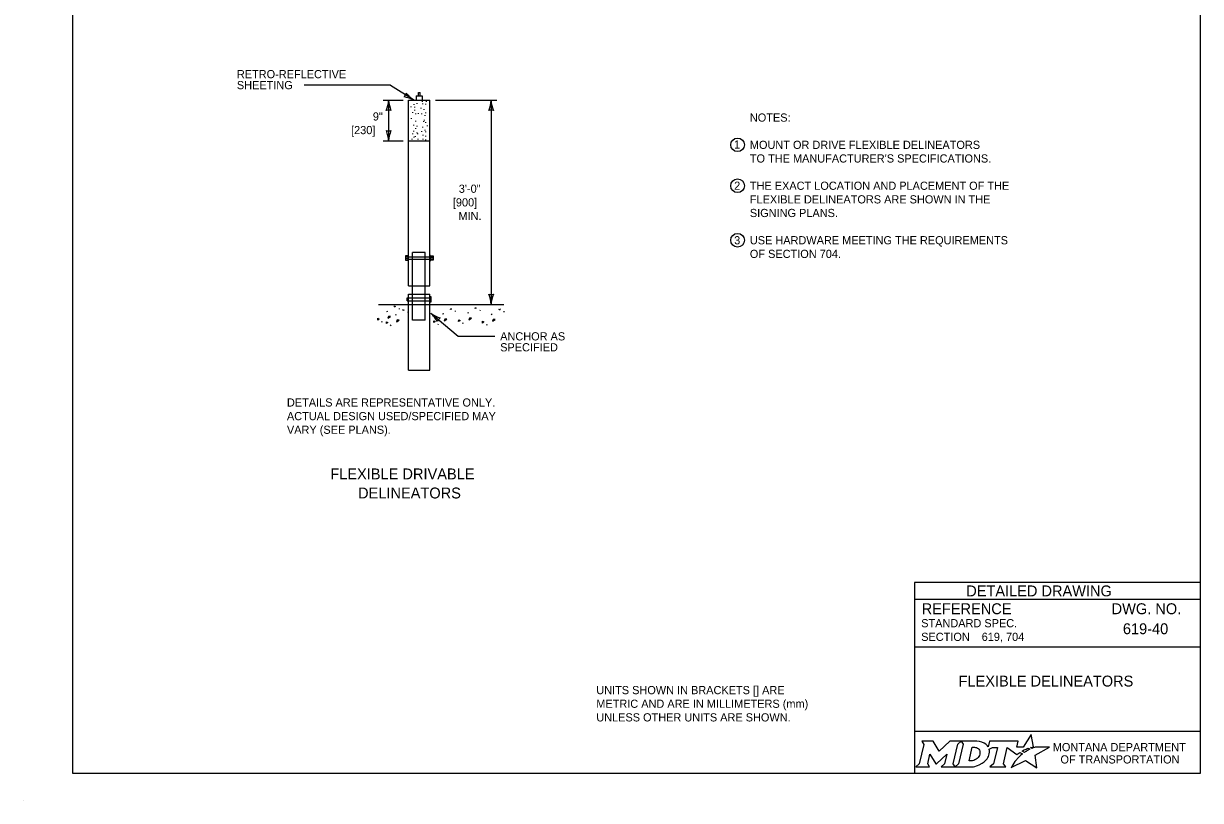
# Model space of a CAD drawing. Extents: x 49991.4 to 50021, y 49987.6 to 50011.4.
# Drawn here: x 49999.98 to 50008.61, y 49999.86 to 50005.56 of the extents above; entities that cross this region are included whole.
import ezdxf

# ---------------------------------------------------------------- set-up
doc = ezdxf.new("R2010")
doc.units = 0
for name, color, linetype in [('Level 1', 7, 'Continuous'), ('Level 2', 7, 'Continuous'), ('Level 3', 7, 'Continuous'), ('Level 4', 7, 'Continuous')]:
    doc.layers.add(name, color=color, linetype=linetype)

msp = doc.modelspace()

# ---------------------------------------------------------------- linework, layer by layer
at = {"layer": 'Level 1'}
for p, q in [((50002.8744, 50005.0555), (50002.8866, 50005.0555)), ((50002.8744, 50005.032), (50002.8744, 50005.0555)), ((50002.8866, 50005.032), (50002.8866, 50005.0555)), ((50002.8029, 50005.001), (50002.9591, 50005.001)), ((50002.8029, 50003.6384), (50002.8029, 50005.001)), ((50002.8226, 50004.9479), (50002.8226, 50004.9528)), ((50002.8293, 50004.9948), (50002.8293, 50004.9997)), ((50002.8429, 50004.9663), (50002.8429, 50004.9712)), ((50002.848, 50004.946), (50002.848, 50004.9509)), ((50002.8583, 50005.032), (50002.8583, 50005.0012)), ((50002.8583, 50005.032), (50002.9035, 50005.032)), ((50002.8656, 50004.9732), (50002.8656, 50004.978)), ((50002.9035, 50005.032), (50002.9035, 50005.0012)), ((50002.9039, 50004.988), (50002.9039, 50004.9929)), ((50002.9074, 50004.971), (50002.9074, 50004.9759)), ((50002.9284, 50004.9697), (50002.9284, 50004.9745)), ((50002.9331, 50004.9873), (50002.9331, 50004.9922)), ((50002.9591, 50003.6384), (50002.9591, 50005.001)), ((50002.8246, 50004.8632), (50002.8246, 50004.868)), ((50002.8348, 50004.9087), (50002.8348, 50004.9135)), ((50002.848, 50004.9257), (50002.848, 50004.9305)), ((50002.8561, 50004.8985), (50002.8561, 50004.9034)), ((50002.8744, 50004.8992), (50002.8744, 50004.904)), ((50002.8948, 50004.9405), (50002.8948, 50004.9454)), ((50002.9005, 50004.8984), (50002.9005, 50004.9033)), ((50002.9169, 50004.9297), (50002.9169, 50004.9345)), ((50002.9236, 50004.8863), (50002.9236, 50004.8912)), ((50002.9304, 50004.9045), (50002.9304, 50004.9094)), ((50002.8415, 50004.8137), (50002.8415, 50004.8185)), ((50002.8554, 50004.7907), (50002.8554, 50004.7955)), ((50002.8561, 50004.8442), (50002.8561, 50004.849)), ((50002.8649, 50004.8069), (50002.8649, 50004.8118)), ((50002.908, 50004.8008), (50002.908, 50004.8057)), ((50002.9141, 50004.8414), (50002.9141, 50004.8463)), ((50002.9203, 50004.8523), (50002.9203, 50004.8572)), ((50002.9236, 50004.7777), (50002.9236, 50004.7825)), ((50002.9284, 50004.8347), (50002.9284, 50004.8395)), ((50002.9413, 50004.8089), (50002.9413, 50004.8138)), ((50002.8029, 50004.701), (50002.9591, 50004.701)), ((50002.8293, 50004.7119), (50002.8293, 50004.7168)), ((50002.8328, 50004.7499), (50002.8328, 50004.7548)), ((50002.8423, 50004.7717), (50002.8423, 50004.7765)), ((50002.8425, 50004.7255), (50002.8425, 50004.7304)), ((50002.8534, 50004.7317), (50002.8534, 50004.7365)), ((50002.8656, 50004.7594), (50002.8656, 50004.7643)), ((50002.8696, 50004.7507), (50002.8696, 50004.7555)), ((50002.8724, 50004.7119), (50002.8724, 50004.7168)), ((50002.9005, 50004.7669), (50002.9005, 50004.7718)), ((50002.9086, 50004.7404), (50002.9086, 50004.7453)), ((50002.9108, 50004.7125), (50002.9108, 50004.7174)), ((50002.9304, 50004.7648), (50002.9304, 50004.7697)), ((50002.9304, 50004.7329), (50002.9304, 50004.7378)), ((50002.9304, 50004.7078), (50002.9304, 50004.7127)), ((50002.7992, 50003.8475), (50002.78, 50003.8475)), ((50002.7992, 50003.8363), (50002.78, 50003.8363)), ((50002.8029, 50003.851), (50002.9591, 50003.851)), ((50002.8029, 50003.8328), (50002.9591, 50003.8328)), ((50002.9629, 50003.8475), (50002.9821, 50003.8475)), ((50002.9629, 50003.8363), (50002.9821, 50003.8363)), ((50002.8029, 50003.6384), (50002.9591, 50003.6384)), ((50002.8029, 50003.576), (50002.9591, 50003.576)), ((50002.8029, 50003.0205), (50002.8029, 50003.576)), ((50002.8322, 50003.578), (50002.8322, 50003.6404)), ((50002.9246, 50003.576), (50002.9246, 50003.6384)), ((50002.9591, 50003.0205), (50002.9591, 50003.576)), ((50002.5807, 50003.5004), (50003.5005, 50003.5004)), ((50002.6972, 50003.483), (50002.7005, 50003.4907)), ((50002.7045, 50003.4848), (50002.6972, 50003.483)), ((50002.7005, 50003.4907), (50002.7045, 50003.4848)), ((50002.7919, 50003.5512), (50002.9591, 50003.5512)), ((50002.7919, 50003.5281), (50002.7919, 50003.5512)), ((50002.7919, 50003.5281), (50002.9591, 50003.5281)), ((50002.9591, 50003.5203), (50002.9682, 50003.5203)), ((50002.5759, 50003.3867), (50002.5767, 50003.4003)), ((50002.5767, 50003.4003), (50002.5862, 50003.3948)), ((50002.6479, 50003.4506), (50002.6402, 50003.4481)), ((50002.6553, 50003.4128), (50002.6502, 50003.3999)), ((50002.6502, 50003.3999), (50002.67, 50003.4124)), ((50002.67, 50003.4124), (50002.6553, 50003.4128)), ((50002.7123, 50003.4255), (50002.7046, 50003.423)), ((50002.735, 50003.4672), (50002.7357, 50003.473)), ((50002.7616, 50003.4579), (50002.7649, 50003.4656)), ((50002.7689, 50003.4597), (50002.7616, 50003.4579)), ((50002.7649, 50003.4656), (50002.7689, 50003.4597)), ((50002.7994, 50003.4421), (50002.8001, 50003.4479)), ((50003.0603, 50003.4322), (50003.0526, 50003.4297)), ((50003.1096, 50003.4646), (50003.1129, 50003.4723)), ((50003.1169, 50003.4664), (50003.1096, 50003.4646)), ((50003.1129, 50003.4723), (50003.1169, 50003.4664)), ((50003.1474, 50003.4488), (50003.1481, 50003.4546)), ((50003.2418, 50003.4398), (50003.2341, 50003.4373)), ((50003.2492, 50003.402), (50003.2441, 50003.3891)), ((50003.2441, 50003.3891), (50003.2639, 50003.4016)), ((50003.2639, 50003.4016), (50003.2492, 50003.402)), ((50003.2911, 50003.4722), (50003.2944, 50003.4799)), ((50003.2984, 50003.474), (50003.2911, 50003.4722)), ((50003.2944, 50003.4799), (50003.2984, 50003.474)), ((50003.3289, 50003.4564), (50003.3296, 50003.4622)), ((50003.4171, 50003.4291), (50003.4094, 50003.4266)), ((50003.4664, 50003.4615), (50003.4697, 50003.4692)), ((50003.4737, 50003.4633), (50003.4664, 50003.4615)), ((50003.4697, 50003.4692), (50003.4737, 50003.4633)), ((50003.5042, 50003.4457), (50003.5049, 50003.4515)), ((50002.5862, 50003.3948), (50002.5759, 50003.3867)), ((50002.6068, 50003.3764), (50002.6042, 50003.3695)), ((50002.6403, 50003.3616), (50002.6411, 50003.3752)), ((50002.6506, 50003.3697), (50002.6403, 50003.3616)), ((50002.6411, 50003.3752), (50002.6506, 50003.3697)), ((50002.6712, 50003.3513), (50002.6686, 50003.3444)), ((50002.7197, 50003.3877), (50002.7146, 50003.3748)), ((50002.7146, 50003.3748), (50002.7344, 50003.3873)), ((50002.7344, 50003.3873), (50002.7197, 50003.3877)), ((50002.9883, 50003.3683), (50002.9891, 50003.3819)), ((50002.9986, 50003.3764), (50002.9883, 50003.3683)), ((50002.9891, 50003.3819), (50002.9986, 50003.3764)), ((50003.0192, 50003.358), (50003.0166, 50003.3511)), ((50003.0677, 50003.3944), (50003.0626, 50003.3815)), ((50003.0626, 50003.3815), (50003.0824, 50003.394)), ((50003.0824, 50003.394), (50003.0677, 50003.3944)), ((50003.1698, 50003.3759), (50003.1706, 50003.3895)), ((50003.1801, 50003.384), (50003.1698, 50003.3759)), ((50003.1706, 50003.3895), (50003.1801, 50003.384)), ((50003.2007, 50003.3656), (50003.1981, 50003.3587)), ((50003.3451, 50003.3652), (50003.3459, 50003.3788)), ((50003.3554, 50003.3733), (50003.3451, 50003.3652)), ((50003.3459, 50003.3788), (50003.3554, 50003.3733)), ((50003.376, 50003.3549), (50003.3734, 50003.348)), ((50003.4245, 50003.3913), (50003.4194, 50003.3784)), ((50003.4194, 50003.3784), (50003.4392, 50003.3909)), ((50003.4392, 50003.3909), (50003.4245, 50003.3913)), ((50002.8029, 50003.0205), (50002.9591, 50003.0205)), ((49999.9766, 49999.8624), (49999.9766, 49999.8624))]:
    msp.add_line(p, q, dxfattribs=at)
msp.add_lwpolyline([(50008.6146, 50011.2628), (50000.3356, 50011.2628), (50000.3356, 50000.0624), (50008.6146, 50000.0624)], close=True, dxfattribs=at)
for points in [[(50002.7992, 50003.8572), (50002.78, 50003.8572), (50002.78, 50003.8253), (50002.7992, 50003.8253)], [(50002.803, 50003.8205), (50002.7992, 50003.8205), (50002.7992, 50003.8613), (50002.803, 50003.8611)], [(50002.9591, 50003.8205), (50002.9629, 50003.8205), (50002.9629, 50003.8613), (50002.9591, 50003.8611)], [(50002.9629, 50003.8572), (50002.9821, 50003.8572), (50002.9821, 50003.8253), (50002.9629, 50003.8253)], [(50002.9682, 50003.5203), (50002.9682, 50003.5581), (50002.9591, 50003.5581)]]:
    msp.add_lwpolyline(points, dxfattribs=at)
at = {"layer": 'Level 2'}
for p, q in [((50008.6146, 50001.4624), (50006.5146, 50001.4624)), ((50006.5146, 50001.4624), (50006.5146, 50000.0624)), ((50008.6146, 50001.3374), (50006.5146, 50001.3374)), ((50008.2507, 50001.1223), (50008.2507, 50001.1223)), ((50008.6146, 50000.9874), (50006.5146, 50000.9874)), ((50007.0089, 50001.0629), (50007.0089, 50001.0629)), ((50007.5646, 50000.7383), (50007.5646, 50000.7383)), ((50008.6146, 50000.3693), (50006.5146, 50000.3693))]:
    msp.add_line(p, q, dxfattribs=at)
for points in [[(50006.5701, 50000.2974), (50006.5842, 50000.274), (50006.5507, 50000.1307), (50006.525, 50000.1082), (50006.6266, 50000.1082), (50006.6131, 50000.131), (50006.6293, 50000.2011), (50006.673, 50000.1321), (50006.6783, 50000.1321), (50006.7534, 50000.2016), (50006.737, 50000.1305), (50006.7123, 50000.1085), (50006.8139, 50000.1085), (50006.8001, 50000.1318), (50006.8333, 50000.2742)], [(50006.8333, 50000.2742), (50006.8586, 50000.2974), (50006.7762, 50000.2974), (50006.6966, 50000.2244), (50006.6521, 50000.2971), (50006.5701, 50000.2974)], [(50006.9722, 50000.2974), (50006.8586, 50000.2974), (50006.8733, 50000.2745), (50006.8394, 50000.1307), (50006.8139, 50000.1085), (50006.9245, 50000.1085)], [(50007.3771, 50000.2447), (50007.3668, 50000.2503), (50007.3784, 50000.2531), (50007.39, 50000.2551), (50007.3726, 50000.3452), (50007.3131, 50000.2539), (50007.2658, 50000.2532), (50007.2761, 50000.2973), (50007.0669, 50000.2974), (50007.0568, 50000.2549), (50007.051, 50000.2632)], [(50006.9962, 50000.2107), (50006.995, 50000.2026), (50006.9918, 50000.1933), (50006.9876, 50000.1851), (50006.982, 50000.1776), (50006.9755, 50000.1707), (50006.9676, 50000.1644), (50006.9593, 50000.1597), (50006.9502, 50000.1558), (50006.9411, 50000.1535), (50006.9319, 50000.1526), (50006.916, 50000.1526), (50006.9396, 50000.2526), (50006.9556, 50000.2526), (50006.9632, 50000.252), (50006.9708, 50000.2501), (50006.9774, 50000.2471), (50006.9835, 50000.2429), (50006.9883, 50000.2379), (50006.992, 50000.2319), (50006.9947, 50000.2257), (50006.9963, 50000.2183), (50006.9963, 50000.2153), (50006.9962, 50000.2107)], [(50007.0636, 50000.2383), (50007.0882, 50000.2514), (50007.1251, 50000.2514), (50007.0965, 50000.1309), (50007.069, 50000.1082), (50007.1852, 50000.1082), (50007.1682, 50000.1311), (50007.1964, 50000.2513), (50007.2677, 50000.1996), (50007.2888, 50000.2147), (50007.3085, 50000.2038)], [(50007.2527, 50000.1479), (50007.2374, 50000.1235), (50007.2327, 50000.116), (50007.2269, 50000.1074), (50007.2246, 50000.1031), (50007.3299, 50000.1562), (50007.4138, 50000.1011), (50007.4007, 50000.1938), (50007.5076, 50000.2522), (50007.4583, 50000.253), (50007.4282, 50000.2534), (50007.4074, 50000.2537), (50007.4006, 50000.2522), (50007.3957, 50000.251), (50007.3873, 50000.2487), (50007.3771, 50000.2447)], [(50007.3267, 50000.2171), (50007.3243, 50000.2154), (50007.306, 50000.225), (50007.3163, 50000.2307), (50007.3204, 50000.2329), (50007.329, 50000.2369), (50007.3347, 50000.2395), (50007.3426, 50000.2425), (50007.3499, 50000.2452), (50007.3617, 50000.2378), (50007.3577, 50000.2357), (50007.3531, 50000.2332), (50007.3489, 50000.231), (50007.3439, 50000.2281), (50007.342, 50000.227), (50007.3393, 50000.2254), (50007.3368, 50000.224), (50007.3345, 50000.2224), (50007.3319, 50000.2206), (50007.3292, 50000.2188), (50007.3267, 50000.2171)], [(50006.9702, 50000.1158), (50006.9786, 50000.1184), (50006.9916, 50000.1238), (50007.012, 50000.1348)], [(50007.2666, 50000.164), (50007.2666, 50000.164)]]:
    msp.add_lwpolyline(points, dxfattribs=at)
for centre in [(50005.2174, 50004.6727), (50005.2174, 50004.3727), (50005.2174, 50003.9727)]:
    msp.add_circle(centre, 0.05, dxfattribs=at)
for centre, radius, start, end in [((50006.9953, 50000.219), 0.0709, 339.53292, 15.85821), ((50006.9513, 50000.2363), 0.1183, 300.91025, 339.13831)]:
    msp.add_arc(centre, radius, start, end, dxfattribs=at)
for centre, major_axis, ratio, start_param, end_param in [((50006.9701, 50000.25), (0.0834, -0.0037), 0.568097, 0.61298, 1.570796), ((50007.0257, 50000.2573), (0.0361, -0.0295), 0.469099, 1.225588, 1.570796), ((50007.2974, 50000.1941), (-0.0112, -0.0097), 0.021651, 3.157348, 6.283185), ((50006.9248, 50000.2568), (0, 0.1484), 0.987302, 3.139398, 3.456847), ((50007.2597, 50000.1559), (-0.00694, -0.00806), 0.008222, 0, 3.137361), ((50007.2764, 50000.1742), (-0.0098, -0.0102), 0.016458, 3.141593, 6.279097)]:
    msp.add_ellipse(centre, major_axis=major_axis, ratio=ratio, start_param=start_param, end_param=end_param, dxfattribs=at)
at = {"layer": 'Level 3'}
for p, q in [((50002.6689, 50005.111), (50002.0373, 50005.111)), ((50002.6689, 50005.111), (50002.8379, 50005.0042)), ((50002.6162, 50005.001), (50002.7629, 50005.001)), ((50002.6562, 50005.001), (50002.6562, 50004.701)), ((50002.9991, 50005.001), (50003.0842, 50005.001)), ((50003.0842, 50005.001), (50003.451, 50005.001)), ((50003.4081, 50005.001), (50003.4081, 50003.5004)), ((50002.6162, 50004.701), (50002.7629, 50004.701)), ((50002.9657, 50003.4375), (50003.1677, 50003.2677)), ((50003.1677, 50003.2677), (50003.4349, 50003.2677))]:
    msp.add_line(p, q, dxfattribs=at)
for centre, radius, start, end in [((50002.7323, 50005.0643), 0.0548, 312.30837, 348.03073), ((50002.962, 50005.1887), 0.2223, 217.62556, 237.80907), ((50002.434, 50005.0102), 0.2223, 337.45601, 357.63952), ((50002.8889, 50005.0125), 0.233, 182.82731, 202.07716), ((50002.7378, 50004.793), 0.233, 62.99686, 82.24671), ((50003.186, 50005.0102), 0.2223, 337.45601, 357.63952), ((50003.6408, 50005.0125), 0.233, 182.82731, 202.07716), ((50002.6562, 50004.8728), 0.0548, 72.13882, 107.86118), ((50003.4081, 50004.8728), 0.0548, 72.13882, 107.86118), ((50002.6562, 50004.8292), 0.0548, 252.13882, 287.86118), ((50002.4235, 50004.6895), 0.233, 2.82731, 22.07716), ((50002.8783, 50004.6918), 0.2223, 157.45601, 177.63952), ((50003.4081, 50003.6286), 0.0548, 252.13882, 287.86118), ((50003.1754, 50003.4889), 0.233, 2.82731, 22.07716), ((50003.6302, 50003.4912), 0.2223, 157.45601, 177.63952), ((50002.8177, 50003.2716), 0.2223, 28.11129, 48.2948), ((50003.1043, 50003.6248), 0.233, 233.48259, 252.73244), ((50003.0648, 50003.3563), 0.0548, 122.7941, 158.51646)]:
    msp.add_arc(centre, radius, start, end, dxfattribs=at)
at = {"layer": 'Level 4'}
for p, q in [((50002.8322, 50003.3859), (50002.8322, 50003.8822)), ((50002.9246, 50003.8822), (50002.8322, 50003.8822)), ((50002.9246, 50003.3859), (50002.9246, 50003.8822)), ((50002.9246, 50003.3859), (50002.8322, 50003.3859))]:
    msp.add_line(p, q, dxfattribs=at)

# ---------------------------------------------------------------- texts
at = {"layer": 'Level 2'}
for s, height, p in [('RETRO-REFLECTIVE ', 0.06, (50001.5424, 50005.1614)), ('SHEETING', 0.06, (50001.5424, 50005.081)), ('9"', 0.06, (50002.5402, 50004.851)), ('NOTES:', 0.06, (50005.3074, 50004.8427)), ('[230]', 0.06, (50002.3805, 50004.751)), ('1', 0.06, (50005.1916, 50004.6453)), ('MOUNT OR DRIVE FLEXIBLE DELINEATORS', 0.06, (50005.3074, 50004.6427)), ("TO THE MANUFACTURER'S SPECIFICATIONS.", 0.06, (50005.3074, 50004.5427)), ('3\'-0"', 0.06, (50003.1712, 50004.3207)), ('2', 0.06, (50005.1922, 50004.3427)), ('THE EXACT LOCATION AND PLACEMENT OF THE', 0.06, (50005.3074, 50004.3427)), ('[900]', 0.06, (50003.1277, 50004.2207)), ('FLEXIBLE DELINEATORS ARE SHOWN IN THE', 0.06, (50005.3074, 50004.2427)), (' MIN.', 0.06, (50003.1464, 50004.1207)), ('SIGNING PLANS. ', 0.06, (50005.3074, 50004.1427)), ('3', 0.06, (50005.1922, 50003.9427)), ('USE HARDWARE MEETING THE REQUIREMENTS', 0.06, (50005.3074, 50003.9427)), ('OF SECTION 704.              ', 0.06, (50005.3074, 50003.8427)), ('ANCHOR AS ', 0.06, (50003.4749, 50003.2377)), ('SPECIFIED', 0.06, (50003.4749, 50003.1573)), ('DETAILS ARE REPRESENTATIVE ONLY.', 0.06, (50001.9098, 50002.7524)), ('ACTUAL DESIGN USED/SPECIFIED MAY', 0.06, (50001.9098, 50002.6524)), ('VARY (SEE PLANS).', 0.06, (50001.9098, 50002.5524)), ('FLEXIBLE DRIVABLE', 0.08, (50002.2282, 50002.2182)), ('DELINEATORS', 0.08, (50002.4318, 50002.0782)), ('DETAILED DRAWING', 0.0799, (50006.8956, 50001.3599)), ('REFERENCE', 0.08, (50006.5682, 50001.229)), ('DWG. NO.', 0.08, (50007.9624, 50001.229)), ('STANDARD SPEC.', 0.06, (50006.5649, 50001.133)), ('619-40', 0.0799, (50008.0454, 50001.0823)), ('SECTION', 0.06, (50006.5649, 50001.033)), ('619, 704', 0.06, (50007.0089, 50001.0329)), ('FLEXIBLE DELINEATORS', 0.0799, (50006.8392, 50000.6983)), ('UNITS SHOWN IN BRACKETS [] ARE ', 0.06, (50004.1803, 50000.6421)), ('METRIC AND ARE IN MILLIMETERS (mm) ', 0.06, (50004.1803, 50000.5421)), ('UNLESS OTHER UNITS ARE SHOWN.', 0.06, (50004.1803, 50000.4421)), ('MONTANA DEPARTMENT', 0.06, (50007.5308, 50000.2236)), ('OF TRANSPORTATION', 0.06, (50007.587, 50000.1336))]:
    msp.add_text(s, height=height, dxfattribs=at).set_placement(p)

doc.saveas('drawing.dxf')
